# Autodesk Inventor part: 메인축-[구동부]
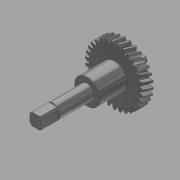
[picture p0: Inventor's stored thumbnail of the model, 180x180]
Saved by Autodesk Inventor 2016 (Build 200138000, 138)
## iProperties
Created: 2017-11
Part Number: 메인축-[구동부]
Material: 강철, 탄소
Document SubType Name: Modeling
Designer: mduedu
Categories: <?xml version="1.0" encoding="UTF-16"?> <MemberInstance><Categories><FamilyTemplate><FamilyTemplateParameter ValueType="xs:double" Id="1" ObjectReferenceKey="da
Density: 7.87 g/cm^3
Mass: 607.365 g
Surface Area: 183.17 cm^2
Volume: 77.1747 cm^3
Appearance: 반광택
CustomPartVersion: 1
Author: mduedu
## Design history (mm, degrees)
sketch "Sketch1"
  geometry: C1 r 34.094 at (0, 0)
  constraints: 1 centre point
  dimensions: "d0" = 68.18712 diameter of C1 (= da_da)
extrude "Extrusion1" new body sketch "Sketch1" distance "d1" = 12 (= da_b); taper "d2" = 0 deg
workplane "Work Plane2"
sketch "Sketch2"
  geometry: C1 r 34.094 at (0, 0) reference; C2 r 32.094 at (0, 0)
  constraints: 1 centre point, 1 coincident
  dimensions: "d3" = 64.18712 diameter of C2 (= da_dw)
feature "피치 지름" sketch "Sketch2" dims "d4" = 10, "d5" = 0
workplane "Work Plane8"
workplane "Work Plane9"
feature "스퍼 기어" dims "d34" = 1.01342 (computed from da_z), "da_b" = 12, "da_d" = 64.18712, "da_aw" = 54.86964, "da_da" = 68.18712, "da_df" = 59.18712, "da_dw" = 64.18712, angle "da_beta" = 15 deg, "da_lefttooth" = 0, "da_righttooth" = 10
sketch "스케치3"
  geometry: C1 r 15 at (0, 0); 1 further point
  constraints: 1 centre point, 1 coincident
  dimensions: "d49" = 30 diameter of C1
extrude "돌출2" join sketch "스케치3" distance "d50" = 32; taper "d51" = 0 deg
sketch "스케치4"
  geometry: C1 r 8.5 at (0, 0); 1 further point
  constraints: 1 centre point, 1 coincident
  dimensions: "d52" = 17 diameter of C1
extrude "돌출3" join sketch "스케치4" distance "d53" = 60; taper "d54" = 0 deg
sketch "스케치5"
  geometry: C1 r 7.5 at (0, 0); 1 further point
  constraints: 1 centre point, 1 coincident
  dimensions: "d55" = 15 diameter of C1
extrude "돌출4" join sketch "스케치5" distance "d56" = 16; taper "d57" = 0 deg
sketch "스케치6"
  geometry: C1 r 4 at (0, 0); 1 further point
  constraints: 1 centre point, 1 coincident
  dimensions: "d58" = 8 diameter of C1
extrude "돌출5" join sketch "스케치6" distance "d59" = 7; taper "d60" = 0 deg
chamfer "모따기1" distance "d61" = 0.5; stored, may be unused: second distance "d62" = 2, angle "d63" = 45 deg
fillet "모깎기1" dims "d64" = 0.5
sketch "스케치7"
  geometry: L1 (-7, -7)-(7, -7); L2 (7, -7)-(7, 7); L3 (7, 7)-(-7, 7); L4 (-7, 7)-(-7, -7); L5 (-7, -7)-(7, 7); L6 (7, -7)-(-7, 7); L7 (-10, -10)-(10, -10); L8 (10, -10)-(10, 10); L9 (10, 10)-(-10, 10); L10 (-10, 10)-(-10, -10); L11 (-10, -10)-(10, 10); L12 (10, -10)-(-10, 10); 1 further point
  constraints: 24 end point, 4 midpoint, 4 parallel, 2 horizontal, 2 perpendicular
  dimensions: "d65" = 14 distance of L3.end L2.end; "d66" = 14 distance of L2.end L1.end; "d67" = 20 distance of L9.end L8.end; "d68" = 20 distance of L8.end L7.end
extrude "돌출6" cut sketch "스케치7" distance "d69" = 20; taper "d70" = 0 deg
body "Solid1"
body "Srf1"
other parameters: "d16" = 54.86964 (= da_aw), "d17" = 0, "d39" = 0, "d41" = 0, "d43" = 54.86964 (= da_aw), "d46" = 54.86964 (= da_aw), "d47" = 0, "d48" = 0
